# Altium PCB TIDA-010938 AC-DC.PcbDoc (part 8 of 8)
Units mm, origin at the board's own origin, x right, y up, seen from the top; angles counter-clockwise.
Board outline 280 x 180.15 mm, 4 copper layers (Top Layer, Layer 1, Layer 2, Bottom Layer), stack 1.787 mm thick; 723 components, 427 nets, 2244 pads, 2295 vias.
Unrouted connection lines stored in the file: 17.
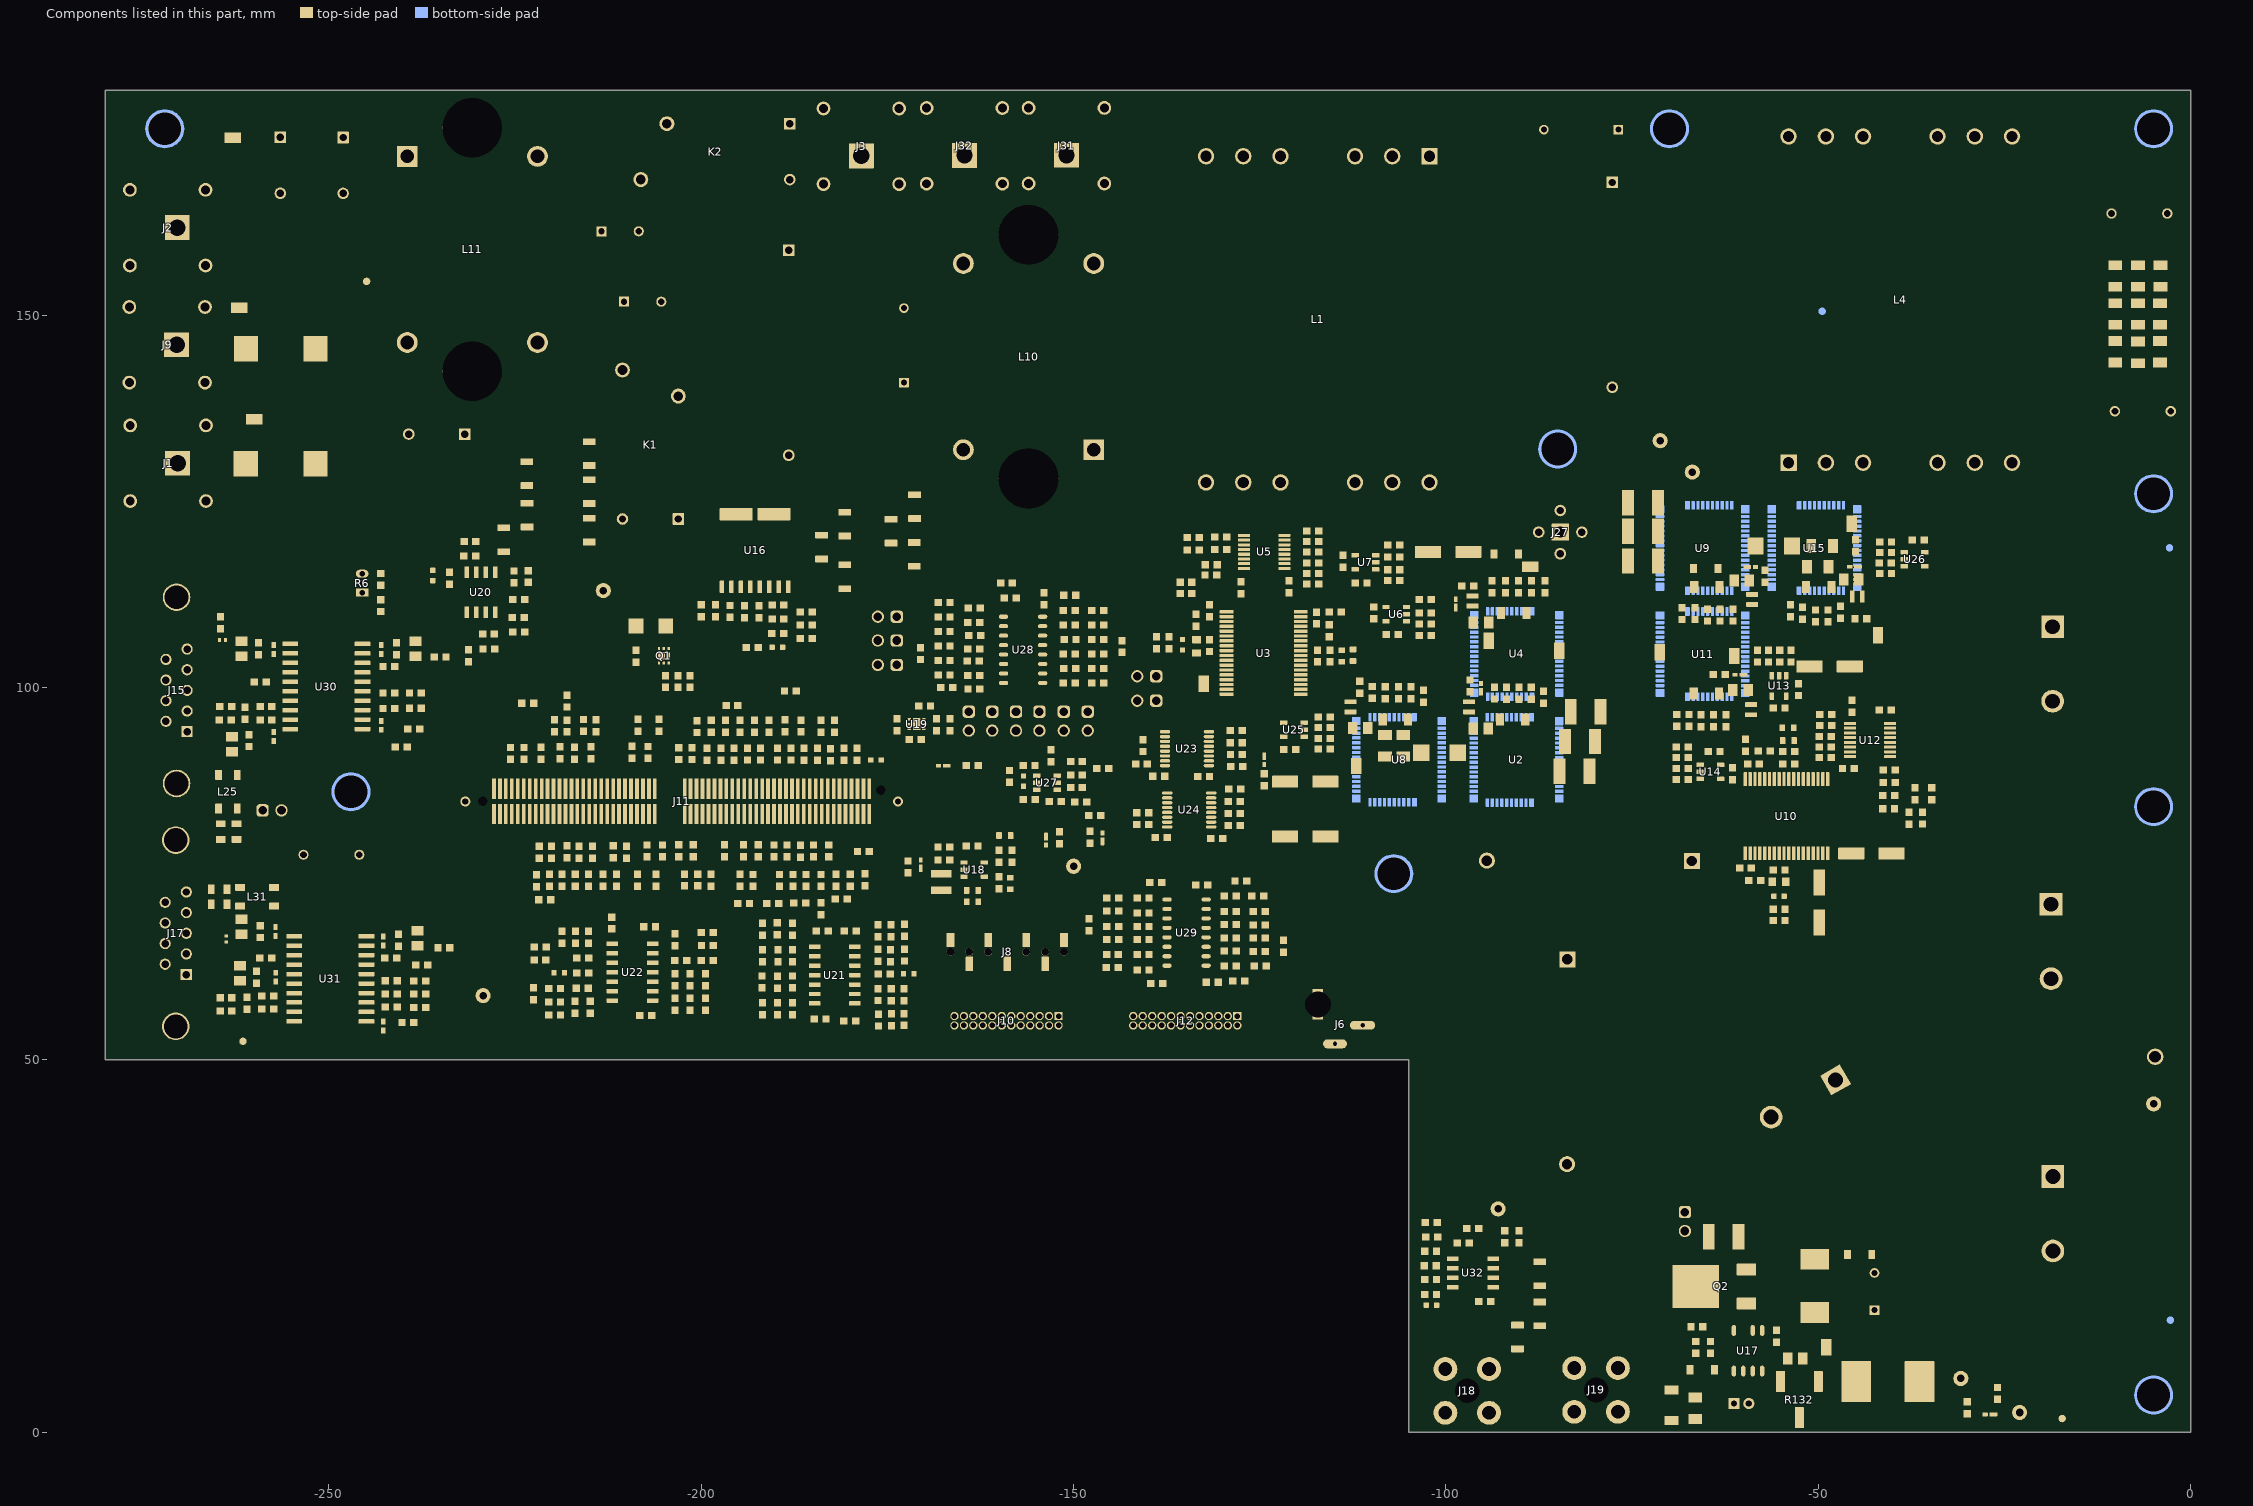
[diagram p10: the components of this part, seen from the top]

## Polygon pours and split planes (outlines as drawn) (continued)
NetR108_2 on Top Layer "TOP_LAYER_NETR108_2_P340" (solid, remove dead copper, pour order 340): -91.5,14 -91.5,15.25 -86.5,15.25 -86.5,14
SW_1 on Top Layer "TOP_LAYER_SW_1_P337" (solid, remove dead copper, pour order 337): -109,125 -109,130 -108.5,130.5 -94,130.5 -94,123 -107,123
VAC_N on Top Layer "TOP_LAYER_VAC_N_P229" (solid, pour order 229): -225.142,177.648 -225.142,162.357 -220.595,157.81 -212,157.81 -212,165.039 -215.238,168.277 -215.238,171.704 -213.815,173.126 -202.358,173.126 -200.148,175.336 -200.148,177.851 -201.571,179.273 -223.516,179.273
ACLOAD_N on Top Layer "TOP_LAYER_ACLOAD_N_P336" (solid, remove dead copper, pour order 336): -210,170 -210,163 -209,162 -209,160 -208.868,159.868 -193.868,159.868 -190,156 -186,156 -186,161 -188,163 -197,163 -204,170
ACLOAD_L on Top Layer "Top Layer-ACLOAD_L" (solid, pour order 334): 17 vertices, not listed, extent -206.625,122.504 -175,174
NetC103_1 on Top Layer "TOP_LAYER_NETC103_1_P331" (solid, remove dead copper, pour order 331): -78,169 -79,168 -80,168 -80,161 -47,161 -46,162 -46,168 -46,177 -57,177 -58,176 -58,173 -63,168 -76,168 -77,169
AC_N on Top Layer "TOP_LAYER_AC_N_P322" (solid, pour order 322): -274.367,132.537 -274.367,128.778 -271.217,125.628 -259.372,125.628 -259,126 -259,132 -258,133 -258,137.795 -260.702,137.795 -265.172,133.325 -273.554,133.325 -274.342,132.537
PE on Top Layer "TOP_LAYER_PE_P214" (solid, pour order 214): -278.294,174.516 -273.816,178.994 -249.196,178.994 -245.767,175.565 -245.767,173.025 -258.467,173.025 -265.223,166.268 -265.223,160.884 -268.347,157.759 -274.189,157.759 -278.294,161.864
NetC116_2 on Top Layer "TOP_LAYER_NETC116_2_P103" (solid, remove dead copper, pour order 103): -51.514,5.424 -48.264,5.424 -48.264,3.924 -42.926,3.924 -42.926,10.643 -50.207,17.924 -53.014,17.924 -53.514,17.424 -53.514,15.424 -52.349,14.26 -52.349,11.088 -52.756,10.682 -52.756,8.166 -51.514,6.924
12V_HVN on Top Layer "TOP_LAYER_12V_HVN_P104" (solid, remove dead copper, pour order 104): -38.354,3.988 -37.79,3.424 -29.514,3.424 -28.514,4.424 -28.514,8.924 -37.014,17.424 -44.014,17.424 -44.75,16.25 -38.354,9.764
NetC229_1 on Top Layer "TOP_LAYER_NETC229_1_P101" (solid, remove dead copper, pour order 101): -69.571,16.698 -69.571,27.448 -69.06,27.958 -63.299,27.958 -63.299,16.698
NetQ2_3 on Top Layer "TOP_LAYER_NETQ2_3_P110" (solid, remove dead copper, pour order 110): -55.268,8.938 -53.442,8.938 -53.442,12.649 -56.058,12.649 -56.311,12.396 -56.311,9.981
"DC Bus-" on Top Layer "TOP_LAYER_DC_BUS-_P089" (solid, remove dead copper, pour order 89): -55.5,78.537 -43.586,78.537 -43.586,75.914 -47.542,71.958 -53.603,71.958 -55.5,73.855
"DC Bus-" on Top Layer "TOP_LAYER_DC_BUS-_P314" (solid, pour order 314): -88.544,121.514 -85.242,124.816 -83.734,124.816 -80.85,121.931 -80.85,120.052 -83.858,117.043 -85.369,117.043 -88.519,120.193
NetR122_2 on Top Layer "TOP_LAYER_NETR122_2_P297" (solid, remove dead copper, pour order 297): -175.815,123.901 -175.815,121.818 -169.871,121.818 -169.871,123.901
NetR123_2 on Top Layer "TOP_LAYER_NETR123_2_P296" (solid, remove dead copper, pour order 296): -175.815,120.269 -175.815,118.186 -169.871,118.186 -169.871,120.269
NetR112_2 on Top Layer "TOP_LAYER_NETR112_2_P295" (solid, remove dead copper, pour order 295): -185.289,117.856 -185.289,115.773 -179.346,115.773 -179.346,117.856
NetR111_2 on Top Layer "TOP_LAYER_NETR111_2_P294" (solid, remove dead copper, pour order 294): -185.213,121.463 -185.213,119.38 -179.269,119.38 -179.269,121.463
VAC_SW+ on Top Layer "TOP_LAYER_VAC_SW+_P243" (solid, pour order 243): 18 vertices, not listed, extent -192.528,122.504 -159.076,160.884
NetR117_2 on Top Layer "TOP_LAYER_NETR117_2_P293" (solid, remove dead copper, pour order 293): -216.7,125.1 -216.7,121.768 -213.509,121.768 -213.509,125.1
NetR116_2 on Top Layer "TOP_LAYER_NETR116_2_P292" (solid, remove dead copper, pour order 292): -217.4,129.841 -217.4,127.759 -212.628,127.759 -212.628,129.841
NetR127_2 on Top Layer "TOP_LAYER_NETR127_2_P291" (solid, remove dead copper, pour order 291): -224.564,127.6 -224.564,123.774 -221.916,123.774 -221.916,127.6
NetR128_2 on Top Layer "TOP_LAYER_NETR128_2_P290" (solid, remove dead copper, pour order 290): -227.91,122.504 -227.91,120.421 -221.967,120.421 -221.967,122.504
NetC103_2 on Top Layer "TOP_LAYER_NETC103_2_P285" (solid, pour order 285): -2.409,144.526 -2.435,144.501 -2.409,144.475 -2.409,142.545 -4.34,140.614 -7.997,140.614 -8.861,139.751 -8.861,135.661 -10.817,135.661 -10.867,135.611 -11.731,136.474 -11.731,143.891 -11.172,144.45
SW_mid on Top Layer "TOP_LAYER_SW_MID_P168" (solid, remove dead copper, pour order 168): -72.5,103.012 -69.5,103.012 -69.5,105.5 -70,106 -72.5,106
12V_HVN on Top Layer "TOP_LAYER_12V_HVN_P183" (solid, remove dead copper, pour order 183): -41.689,25.269 -38.439,25.269 -38.439,28.019 -41.689,28.019
NetR77_1 on Top Layer "TOP_LAYER_NETR77_1_P272" (solid, pour order 272): -11.89,149.403 -2.696,149.403 -2.696,145.821 -11.916,145.821
NetR185_1 on Top Layer "TOP_LAYER_NETR185_1_P271" (solid, pour order 271): -11.78,154.507 -2.585,154.507 -2.585,150.925 -11.806,150.925
NetC103_1 on Top Layer "TOP_LAYER_NETC103_1_P270" (solid, pour order 270): -12.182,164.923 -9.928,164.923 -8.886,163.881 -8.886,158.775 -3.527,158.775 -2.409,157.658 -2.409,156.007 -11.604,156.007 -12.188,156.591 -12.188,164.897
"DC Bus-" on Top Layer "TOP_LAYER_DC_BUS-_P177" (solid, remove dead copper, pour order 177): -130.5,109.5 -130.5,111.5 -128,111.5 -128,109.5
"DC Bus-" on Top Layer "TOP_LAYER_DC_BUS-_P266" (solid, remove dead copper, pour order 266): -54.214,112.837 -54.214,114.837 -53.964,115.087 -49.464,115.087 -51.534,113.017 -51.534,112.837
SW_2 on Top Layer "TOP_LAYER_SW_2_P051" (solid, remove dead copper, pour order 51): -53.657,86.683 -54.157,87.183 -54.157,88.683 -53.657,88.683 -53.657,94.869 -52.843,94.869 -52.307,94.333 -52.307,91.833 -51.857,91.383 -50.11,89.637 -48.957,89.637 -47.503,88.183 -46.657,88.183 -46.657,86.683
SW_2 on Top Layer "TOP_LAYER_SW_2_P052" (solid, remove dead copper, pour order 52): -56.816,86.759 -56.816,89.059 -57.016,89.259 -57.016,90.159 -56.716,90.459 -56.016,90.459 -55.616,90.059 -55.616,88.659 -55.716,88.559 -55.716,86.759
SW_2 on Top Layer "TOP_LAYER_SW_2_P053" (solid, remove dead copper, pour order 53): -68.589,87.125 -69.789,87.125 -69.789,95.253 -65.539,95.253 -65.189,94.903 -65.189,93.853 -67.789,93.853 -68.589,93.053
"DC Bus+" on Top Layer "TOP_LAYER_DC_BUS+_P063" (solid, remove dead copper, pour order 63): -72.768,114.582 -73.25,114.1 -73.25,112.975 -72.768,112.5 -72.768,112 -70.5,112 -70,112.5 -70,115.739 -68.818,116.921 -68.818,126.318 -69.921,127.421 -72.218,127.421 -72.768,126.871
SW_2 on Top Layer "TOP_LAYER_SW_2_P074" (solid, remove dead copper, pour order 74): -64.14,100.171 -60.965,100.171 -60.965,100.662 -62.881,100.662 -63.39,101.171 -63.39,102.171 -63.64,102.421 -65.89,102.421 -68.64,99.671 -68.64,98.171 -65.983,98.171 -65.983,99.143 -65.705,99.421 -64.89,99.421
SW_2 on Top Layer "TOP_LAYER_SW_2_P199" (solid, remove dead copper, pour order 199): -47.919,104.771 -47.919,99.25 -44.125,99.25 -44.125,104.771
NetC103_2 on Top Layer "TOP_LAYER_NETC103_2_P250" (solid, pour order 250): 20 vertices, not listed, extent -150.771,133.325 -8.861,174.422
VAC_L on Top Layer "TOP_LAYER_VAC_L_P233" (solid, pour order 233): -225.026,149.24 -220.965,153.3 -209.216,153.3 -209.216,141.046 -211.553,138.709 -224.961,138.709
NetF1_1 on Top Layer "TOP_LAYER_NETF1_1_P221" (solid, pour order 221): 23 vertices, not listed, extent -259.635,130.86 -236.572,167.64
NetF2_1 on Top Layer "TOP_LAYER_NETF2_1_P222" (solid, pour order 222): -251.23,167.649 -251.221,167.64 -244.903,167.64 -244.903,167.792 -242.185,170.51 -242.185,174.625 -237.943,174.625 -233.905,170.586 -233.905,165.354 -237.68,161.578 -251.203,161.578
SN_Relays_PreCharge on Top Layer "TOP_LAYER_SN_RELAYS_PRECHARGE_P043" (solid, remove dead copper, pour order 43): -204.425,114.1 -202.402,114.102 -201.375,113.075 -201.375,108.45 -203.625,106.2 -204.5,106.2 -204.775,105.925 -204.775,102.725 -204.975,102.525 -206.025,102.525 -206.35,102.85 -206.35,112.225 -204.475,114.1
SW_1 on Top Layer "TOP_LAYER_SW_1_P056" (solid, remove dead copper, pour order 56): -117,99 -114.5,101.5 -114.5,102.5 -113.5,103.5 -112,103.5 -112,104 -120.5,104 -120.5,99
SW_1 on Top Layer "TOP_LAYER_SW_1_P200" (solid, remove dead copper, pour order 200): -103,115 -104,116 -105,117 -105,121 -101,121 -100,120 -100,115
SW_1 on Top Layer "TOP_LAYER_SW_1_P181" (solid, remove dead copper, pour order 181): -91.75,93.75 -89,93.75 -88.5,94.25 -88.5,96.5 -88.65,96.65 -89.9,96.65 -90.75,95.8 -91.75,95.8
SW_1 on Top Layer "TOP_LAYER_SW_1_P179" (solid, remove dead copper, pour order 179): -122.5,121.75 -122.5,120.295 -120.955,120.295 -120.25,121 -120.25,121.5 -120.5,121.75
"DC Bus-" on Top Layer "TOP_LAYER_DC_BUS-_P176" (solid, remove dead copper, pour order 176): -128.5,98.5 -132.5,98.5 -132.5,102.5 -131.5,103.5 -131.5,105.05 -131.05,105.05 -131.05,105.625 -128.625,105.625 -128.5,105.5
SW_1 on Top Layer "TOP_LAYER_SW_1_P174" (solid, remove dead copper, pour order 174): -90.725,114.075 -90.75,114.1 -90.75,119 -89.5,119 -86.7,116.2 -86.7,114.075
"DC Bus-" on Top Layer "TOP_LAYER_DC_BUS-_P173" (solid, remove dead copper, pour order 173): -189.25,106.25 -189.25,111.5 -186.75,111.5 -186.446,111.196 -186.446,109.377 -186.76,109.064 -186.794,109.098 -187.446,109.098 -187.446,106.354 -187.55,106.25
"DC Bus-" on Top Layer "TOP_LAYER_DC_BUS-_P172" (solid, remove dead copper, pour order 172): -122,78.75 -121.5,78.25 -119.75,78.25 -118.75,79.25 -118.75,88.75 -119.5,89.5 -120.75,89.5 -121.5,88.75 -121.5,85.75 -121.75,85.5 -123.25,85.5 -124,84.75 -124,78.75
SW_mid on Top Layer "TOP_LAYER_SW_MID_P166" (solid, remove dead copper, pour order 166): -86.25,103.25 -83.75,103.25 -83.75,106.75 -86.25,106.75
SW_1 on Top Layer "TOP_LAYER_SW_1_P076" (solid, remove dead copper, pour order 76): -95,104.953 -93.25,104.953 -93.25,107.5 -93,107.75 -89,107.75 -88.25,108.5 -88.25,110.604 -88.625,110.979 -91.75,110.979 -91.75,109.175 -91.9,109.025 -93.3,109.025 -93.5,109.225 -93.5,110 -95,110
"DC Bus-" on Layer 2 "Layer 2-DC Bus- 1" (solid, remove dead copper, pour order 196): 73 vertices, not listed, extent -246.6,0.523 -21.869,123.469
"DC Bus-" on Layer 2 "Layer 2-DC Bus-" (solid, pour order 309): 34 vertices, not listed, extent -114,62.5 -40,139
NetF2_1 on Layer 2 "LAYER_2_NETF2_1_P228" (solid, pour order 228): 25 vertices, not listed, extent -254.682,125.197 -228.952,174.625
"DC Bus-" on Layer 2 "LAYER_2_DC_BUS-_P361" (solid, remove dead copper, pour order 361): -72.5,1 -72.5,17.5 -78,17.5 -86,9.5 -86,1
NetC229_1 on Layer 2 "LAYER_2_NETC229_1_P352" (solid, remove dead copper, pour order 352): -70,16.5 -70,27.5 -63,27.5 -63,16.5
SW_1 on Layer 2 "LAYER_2_SW_1_P339" (solid, remove dead copper, pour order 339): -109,125 -109,130 -108.5,130.5 -94,130.5 -94,123 -107,123
ACLOAD_L on Layer 2 "LAYER_2_ACLOAD_L_P335" (solid, remove dead copper, pour order 335): -197,124 -193,124 -193,135 -177,151 -177,159 -175,161 -175,174 -182,174 -182,157 -197,142
NetC103_1 on Layer 2 "LAYER_2_NETC103_1_P332" (solid, remove dead copper, pour order 332): -78,169 -79,168 -80,168 -80,161 -47,161 -46,162 -46,168 -46,177 -57,177 -58,176 -58,173 -63,168 -76,168 -77,169
VAC_N on Layer 2 "LAYER_2_VAC_N_P302" (solid, pour order 302): -225.142,177.648 -225.142,162.357 -220.595,157.81 -212,157.81 -212,165.039 -215.238,168.277 -215.238,171.704 -213.815,173.126 -202.358,173.126 -200.148,175.336 -200.148,177.851 -201.571,179.273 -223.516,179.273
AC_L on Layer 2 "LAYER_2_AC_L_P325" (solid, pour order 325): -275.002,148.768 -275.002,145.009 -271.852,141.859 -259,141.859 -259,153.975 -261.388,153.975 -265.807,149.555 -274.189,149.555 -274.977,148.768
AC_N on Layer 2 "LAYER_2_AC_N_P321" (solid, pour order 321): -274.367,132.537 -274.367,128.778 -271.217,125.628 -259.372,125.628 -259,126 -259,132 -258,133 -258,137.795 -260.702,137.795 -265.172,133.325 -273.554,133.325 -274.342,132.537
NetC103_2 on Layer 2 "LAYER_2_NETC103_2_P251" (solid, pour order 251): 21 vertices, not listed, extent -150.771,133.325 -8.861,174.422
"DC Bus+" on Layer 2 "LAYER_2_DC_BUS+_P097" (solid, remove dead copper, pour order 97): -91.335,0.575 -102.688,0.575 -102.688,11.24 -102.062,11.709 -94.586,11.709 -83,23.295 -83,30 -86,33 -86,38.5 -73,38.5 -73,25.497 -91.335,7.163
"DC Bus-" on Layer 2 "LAYER_2_DC_BUS-_P119" (solid, remove dead copper, pour order 119): -24.725,112 -12.45,112 -12.45,14 -24.725,14
PE3 on Layer 2 "LAYER_2_PE3_P269" (solid, pour order 269): 17 vertices, not listed, extent -10.436,131.928 -0.631,178.714
SW_1 on Layer 2 "Layer 2-SW_1" (solid, remove dead copper, pour order 55): 27 vertices, not listed, extent -122.5,94 -86.7,122
SW_2 on Layer 2 "LAYER_2_SW_2_P050" (solid, remove dead copper, pour order 50): 30 vertices, not listed, extent -69.776,86.6 -44.776,116.2
VAC_SW+ on Layer 2 "LAYER_2_VAC_SW+_P275" (solid, pour order 275): 20 vertices, not listed, extent -192.528,122.504 -159.076,160.884
PE2 on Layer 2 "Layer 2-PE2" (solid, pour order 257): 26 vertices, not listed, extent -174,150 -65.757,178.998
PE on Layer 2 "LAYER_2_PE_P217" (solid, pour order 217): -278.294,174.516 -273.816,178.994 -249.196,178.994 -245.767,175.565 -245.767,173.025 -246.656,172.136 -259.356,172.136 -265.223,166.268 -265.223,160.884 -268.347,157.759 -274.189,157.759 -278.294,161.864
GND_ISO_COMM on Layer 2 "LAYER_2_GND_ISO_COMM_P045" (solid, remove dead copper, pour order 45): -279.7,116.5 -277.4,118.8 -258.3,118.8 -253.6,114.1 -253.6,50.7 -278.3,50.7 -279.7,52.1

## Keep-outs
Keep-Out Layer:
  text ".Layer_Name" at -281.017,-104.177 h0.5

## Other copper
Top Layer:
  pour cut-out: -114.5,74.55 ccw(c-107.2,74.55) -107.2,67.25 ccw(c-107.2,74.55) -99.9,74.55 ccw(c-107.2,74.55) -107.2,81.85 ccw(c-107.2,74.55)
  pour cut-out: -92.213,131.826 ccw(c-84.913,131.826) -84.913,124.526 ccw(c-84.913,131.826) -77.613,131.826 ccw(c-84.913,131.826) -84.913,139.126 ccw(c-84.913,131.826)
  pour cut-out: -87.75,36 ccw(c-83.75,36) -83.75,32 ccw(c-83.75,36) -79.75,36 ccw(c-83.75,36) -83.75,40 ccw(c-83.75,36)
  pour cut-out: -8.792,50.419 ccw(c-4.792,50.419) -4.792,46.419 ccw(c-4.792,50.419) -0.792,50.419 ccw(c-4.792,50.419) -4.792,54.419 ccw(c-4.792,50.419)
  pour cut-out: -12.565,5.284 ccw(c-5.265,5.284) -5.265,-2.016 ccw(c-5.265,5.284) 2.035,5.284 ccw(c-5.265,5.284) -5.265,12.584 ccw(c-5.265,5.284)
  pour cut-out: -11.994,84.199 ccw(c-4.694,84.199) -4.694,76.899 ccw(c-4.694,84.199) 2.606,84.199 ccw(c-4.694,84.199) -4.694,91.499 ccw(c-4.694,84.199)
  pour cut-out: -22.55,98.15 ccw(c-18.55,98.15) -18.55,94.15 ccw(c-18.55,98.15) -14.55,98.15 ccw(c-18.55,98.15) -18.55,102.15 ccw(c-18.55,98.15)
  pour cut-out: -22.775,60.9 ccw(c-18.775,60.9) -18.775,56.9 ccw(c-18.775,60.9) -14.775,60.9 ccw(c-18.775,60.9) -18.775,64.9 ccw(c-18.775,60.9)
  pour cut-out: -22.525,24.35 ccw(c-18.525,24.35) -18.525,20.35 ccw(c-18.525,24.35) -14.525,24.35 ccw(c-18.525,24.35) -18.525,28.35 ccw(c-18.525,24.35)
  pour cut-out: -60.344,42.311 ccw(c-56.344,42.311) -56.344,38.311 ccw(c-56.344,42.311) -52.344,42.311 ccw(c-56.344,42.311) -56.344,46.311 ccw(c-56.344,42.311)
  pour cut-out: -254.4,86.1 ccw(c-247.1,86.1) -247.1,78.8 ccw(c-247.1,86.1) -239.8,86.1 ccw(c-247.1,86.1) -247.1,93.4 ccw(c-247.1,86.1)
  pour cut-out: -254.4,86.1 ccw(c-247.1,86.1) -247.1,78.8 ccw(c-247.1,86.1) -239.8,86.1 ccw(c-247.1,86.1) -247.1,93.4 ccw(c-247.1,86.1)
  pour cut-out: -62.538,61.613 -61.038,61.613 -61.038,45.113 -62.538,45.113
  pour cut-out: -73.338,61.613 -71.838,61.613 -71.838,45.113 -73.338,45.113
  pour cut-out: -86.233,122.936 -82.956,122.936 -82.575,122.555 -82.575,119.151 -82.982,118.745 -86.385,118.745 -86.741,119.101 -86.741,122.479
  pour cut-out: -198.217,122.446 -198.217,124.605 -198.217,124.783 -198.217,124.935 -197.505,124.935 -197.505,122.446
  pour cut-out: -188.007,122.428 -188.007,124.587 -188.007,124.765 -188.007,124.917 -187.296,124.917 -187.296,122.428
  pour cut-out: -184.603,174.523 -184.476,174.65 -184.502,174.65 -184.527,174.676
  pour cut-out: -84.75,61.5 -83.25,61.5 -83.25,45 -84.75,45
  text ".Layer_Name" at -281.017,-104.177 h0.5
Layer 1:
  pour cut-out: -8.994,44.094 ccw(c-4.994,44.094) -4.994,40.094 ccw(c-4.994,44.094) -0.994,44.094 ccw(c-4.994,44.094) -4.994,48.094 ccw(c-4.994,44.094)
  pour cut-out: -22.55,108.15 ccw(c-18.55,108.15) -18.55,104.15 ccw(c-18.55,108.15) -14.55,108.15 ccw(c-18.55,108.15) -18.55,112.15 ccw(c-18.55,108.15)
  pour cut-out: -22.775,70.9 ccw(c-18.775,70.9) -18.775,66.9 ccw(c-18.775,70.9) -14.775,70.9 ccw(c-18.775,70.9) -18.775,74.9 ccw(c-18.775,70.9)
  pour cut-out: -22.525,34.35 ccw(c-18.525,34.35) -18.525,30.35 ccw(c-18.525,34.35) -14.525,34.35 ccw(c-18.525,34.35) -18.525,38.35 ccw(c-18.525,34.35)
  pour cut-out: -51.684,47.311 ccw(c-47.684,47.311) -47.684,43.311 ccw(c-47.684,47.311) -43.684,47.311 ccw(c-47.684,47.311) -47.684,51.311 ccw(c-47.684,47.311)
  pour cut-out: -87.7,63.5 ccw(c-83.7,63.5) -83.7,59.5 ccw(c-83.7,63.5) -79.7,63.5 ccw(c-83.7,63.5) -83.7,67.5 ccw(c-83.7,63.5)
  pour cut-out: -254.4,86.1 ccw(c-247.1,86.1) -247.1,78.8 ccw(c-247.1,86.1) -239.8,86.1 ccw(c-247.1,86.1) -247.1,93.4 ccw(c-247.1,86.1)
  pour cut-out: -63.05,62.1 -60.55,62.1 -60.55,44.737 -63.05,44.737
  pour cut-out: -73.85,62.2 -71.35,62.2 -71.35,44.737 -73.85,44.737
  pour cut-out: -85.25,61.5 -82.75,61.5 -82.75,44.737 -85.25,44.737
Layer 2:
  pour cut-out: -92.213,131.826 ccw(c-84.913,131.826) -84.913,124.526 ccw(c-84.913,131.826) -77.613,131.826 ccw(c-84.913,131.826) -84.913,139.126 ccw(c-84.913,131.826)
  pour cut-out: -22.55,98.15 ccw(c-18.55,98.15) -18.55,94.15 ccw(c-18.55,98.15) -14.55,98.15 ccw(c-18.55,98.15) -18.55,102.15 ccw(c-18.55,98.15)
  pour cut-out: -22.775,60.9 ccw(c-18.775,60.9) -18.775,56.9 ccw(c-18.775,60.9) -14.775,60.9 ccw(c-18.775,60.9) -18.775,64.9 ccw(c-18.775,60.9)
  pour cut-out: -22.525,24.35 ccw(c-18.525,24.35) -18.525,20.35 ccw(c-18.525,24.35) -14.525,24.35 ccw(c-18.525,24.35) -18.525,28.35 ccw(c-18.525,24.35)
  pour cut-out: -98.5,76.75 ccw(c-94.5,76.75) -94.5,72.75 ccw(c-94.5,76.75) -90.5,76.75 ccw(c-94.5,76.75) -94.5,80.75 ccw(c-94.5,76.75)
  pour cut-out: -254.4,86.1 ccw(c-247.1,86.1) -247.1,78.8 ccw(c-247.1,86.1) -239.8,86.1 ccw(c-247.1,86.1) -247.1,93.4 ccw(c-247.1,86.1)
  pour cut-out: -57.069,127.27 -57.069,133.27 -45.8,133.27 -45.8,127.27
  pour cut-out: -69.05,127 -69.05,131.183 -64.6,131.183 -64.6,127
  pour cut-out: -188.001,122.439 -188.001,124.598 -188.001,124.776 -188.001,124.928 -187.29,124.928 -187.29,122.439
  pour cut-out: -58,45 -54,45 -49,50 -44.5,50 -44.5,47 -52,39.5 -58,39.5 -59.5,41 -59.5,43.5
Bottom Layer:
  pour cut-out: -57.504,101.454 ccw(c-57.004,101.454) -57.004,100.954 ccw(c-57.004,101.454) -56.504,101.454 ccw(c-57.004,101.454) -57.004,101.954 ccw(c-57.004,101.454)
  pour cut-out: -102.454,105.804 ccw(c-101.954,105.804) -101.954,105.304 ccw(c-101.954,105.804) -101.454,105.804 ccw(c-101.954,105.804) -101.954,106.304 ccw(c-101.954,105.804)
  pour cut-out: -104.504,116.954 ccw(c-104.004,116.954) -104.004,116.454 ccw(c-104.004,116.954) -103.504,116.954 ccw(c-104.004,116.954) -104.004,117.454 ccw(c-104.004,116.954)
  pour cut-out: -103.504,116.954 ccw(c-103.004,116.954) -103.004,116.454 ccw(c-103.004,116.954) -102.504,116.954 ccw(c-103.004,116.954) -103.004,117.454 ccw(c-103.004,116.954)
  pour cut-out: -103.504,115.954 ccw(c-103.004,115.954) -103.004,115.454 ccw(c-103.004,115.954) -102.504,115.954 ccw(c-103.004,115.954) -103.004,116.454 ccw(c-103.004,115.954)
  pour cut-out: -102.504,115.954 ccw(c-102.004,115.954) -102.004,115.454 ccw(c-102.004,115.954) -101.504,115.954 ccw(c-102.004,115.954) -102.004,116.454 ccw(c-102.004,115.954)
  pour cut-out: -102.496,117.046 ccw(c-101.996,117.046) -101.996,116.546 ccw(c-101.996,117.046) -101.496,117.046 ccw(c-101.996,117.046) -101.996,117.546 ccw(c-101.996,117.046)
  pour cut-out: -102.524,119.528 ccw(c-102.024,119.528) -102.024,119.028 ccw(c-102.024,119.528) -101.524,119.528 ccw(c-102.024,119.528) -102.024,120.028 ccw(c-102.024,119.528)
  pour cut-out: -22.525,34.35 ccw(c-18.525,34.35) -18.525,30.35 ccw(c-18.525,34.35) -14.525,34.35 ccw(c-18.525,34.35) -18.525,38.35 ccw(c-18.525,34.35)
  pour cut-out: -92.213,131.826 ccw(c-84.913,131.826) -84.913,124.526 ccw(c-84.913,131.826) -77.613,131.826 ccw(c-84.913,131.826) -84.913,139.126 ccw(c-84.913,131.826)
  pour cut-out: -114.724,74.66 ccw(c-107.424,74.66) -107.424,67.36 ccw(c-107.424,74.66) -100.124,74.66 ccw(c-107.424,74.66) -107.424,81.96 ccw(c-107.424,74.66)
  pour cut-out: -12.444,84.149 ccw(c-5.144,84.149) -5.144,76.849 ccw(c-5.144,84.149) 2.156,84.149 ccw(c-5.144,84.149) -5.144,91.449 ccw(c-5.144,84.149)
  pour cut-out: -22.55,108.15 ccw(c-18.55,108.15) -18.55,104.15 ccw(c-18.55,108.15) -14.55,108.15 ccw(c-18.55,108.15) -18.55,112.15 ccw(c-18.55,108.15)
  pour cut-out: -22.775,70.9 ccw(c-18.775,70.9) -18.775,66.9 ccw(c-18.775,70.9) -14.775,70.9 ccw(c-18.775,70.9) -18.775,74.9 ccw(c-18.775,70.9)
  pour cut-out: -57.794,112.174 ccw(c-57.294,112.174) -57.294,111.674 ccw(c-57.294,112.174) -56.794,112.174 ccw(c-57.294,112.174) -57.294,112.674 ccw(c-57.294,112.174)
  pour cut-out: -63.054,114.954 ccw(c-62.554,114.954) -62.554,114.454 ccw(c-62.554,114.954) -62.054,114.954 ccw(c-62.554,114.954) -62.554,115.454 ccw(c-62.554,114.954)
  pour cut-out: -61.994,108.124 ccw(c-61.494,108.124) -61.494,107.624 ccw(c-61.494,108.124) -60.994,108.124 ccw(c-61.494,108.124) -61.494,108.624 ccw(c-61.494,108.124)
  pour cut-out: -65.386,108.124 ccw(c-64.886,108.124) -64.886,107.624 ccw(c-64.886,108.124) -64.386,108.124 ccw(c-64.886,108.124) -64.886,108.624 ccw(c-64.886,108.124)
  pour cut-out: -96.304,98.054 ccw(c-95.804,98.054) -95.804,97.554 ccw(c-95.804,98.054) -95.304,98.054 ccw(c-95.804,98.054) -95.804,98.554 ccw(c-95.804,98.054)
  pour cut-out: -101.466,111.566 ccw(c-100.966,111.566) -100.966,111.066 ccw(c-100.966,111.566) -100.466,111.566 ccw(c-100.966,111.566) -100.966,112.066 ccw(c-100.966,111.566)
  pour cut-out: -101.5,119.5 ccw(c-101,119.5) -101,119 ccw(c-101,119.5) -100.5,119.5 ccw(c-101,119.5) -101,120 ccw(c-101,119.5)
  pour cut-out: -101.504,115.954 ccw(c-101.004,115.954) -101.004,115.454 ccw(c-101.004,115.954) -100.504,115.954 ccw(c-101.004,115.954) -101.004,116.454 ccw(c-101.004,115.954)
  pour cut-out: -96.971,114.58 ccw(c-96.471,114.58) -96.471,114.08 ccw(c-96.471,114.58) -95.971,114.58 ccw(c-96.471,114.58) -96.471,115.08 ccw(c-96.471,114.58)
  pour cut-out: -89.55,117.005 ccw(c-89.05,117.005) -89.05,116.505 ccw(c-89.05,117.005) -88.55,117.005 ccw(c-89.05,117.005) -89.05,117.505 ccw(c-89.05,117.005)
  pour cut-out: -88.55,117.005 ccw(c-88.05,117.005) -88.05,116.505 ccw(c-88.05,117.005) -87.55,117.005 ccw(c-88.05,117.005) -88.05,117.505 ccw(c-88.05,117.005)
  pour cut-out: -88.55,116.005 ccw(c-88.05,116.005) -88.05,115.505 ccw(c-88.05,116.005) -87.55,116.005 ccw(c-88.05,116.005) -88.05,116.505 ccw(c-88.05,116.005)
  pour cut-out: -89.054,115.604 ccw(c-88.554,115.604) -88.554,115.104 ccw(c-88.554,115.604) -88.054,115.604 ccw(c-88.554,115.604) -88.554,116.104 ccw(c-88.554,115.604)
  pour cut-out: -89.55,116.005 ccw(c-89.05,116.005) -89.05,115.505 ccw(c-89.05,116.005) -88.55,116.005 ccw(c-89.05,116.005) -89.05,116.505 ccw(c-89.05,116.005)
  pour cut-out: -93.471,101.333 ccw(c-92.971,101.333) -92.971,100.833 ccw(c-92.971,101.333) -92.471,101.333 ccw(c-92.971,101.333) -92.971,101.833 ccw(c-92.971,101.333)
  pour cut-out: -90.704,101.354 ccw(c-90.204,101.354) -90.204,100.854 ccw(c-90.204,101.354) -89.704,101.354 ccw(c-90.204,101.354) -90.204,101.854 ccw(c-90.204,101.354)
  pour cut-out: -254.5,86.55 ccw(c-247.2,86.55) -247.2,79.25 ccw(c-247.2,86.55) -239.9,86.55 ccw(c-247.2,86.55) -247.2,93.85 ccw(c-247.2,86.55)
  pour cut-out: -87,115 -90,115 -90,126.5 -87,126.5
  pour cut-out: -198.217,122.446 -198.217,124.605 -198.217,124.783 -198.217,124.935 -197.505,124.935 -197.505,122.446
  pour cut-out: -86.534,100.69 -86.534,98.552 -85.366,98.552 -85.34,98.577 -85.69,98.927 -85.69,100 -85.844,100
  pour cut-out: -48.5,50 -43.949,50 -43.949,43.303 -49.355,37.897 -58.283,37.897 -60.449,40.063 -60.449,44.803 -59.449,45.803 -52.697,45.803
  text ".Layer_Name" at -281.017,-104.177 h0.5

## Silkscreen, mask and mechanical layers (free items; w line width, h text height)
Top Overlay:
  drawing of 188 lines, arcs and shapes, not listed
  text "PE" at -143,176.1 h2
  text "PE" at -270,170 h2
  text "L1" at -184.4,163.6 h2
  text "N" at -170.5,161.8 h2.1
  text "L1" at -263.6,153 h2
  text "N" at -263.3,135.5 h2.1
  text "DC Bus-" at -69.592,134.163 h1.52
  text "SW2" at -71.98,128.6 h1.52
  text "SW1" at -91.665,124.409 h1.52
  text "S5" at -140.848,120.152 h0.89
  text "S1" at -140.848,117.652 h0.89
  text "DC Bus-" at -80.819,106.35 h1.52
  text "S6" at -45.848,85.652 h0.89
  text "S3" at -44.348,82.152 h0.89
  text ".PRJ_Number" at -216.728,50.824 h3.05
  text "VER: .PCB_Rev" at -189.652,50.789 h3.05
  text "DC Bus+" at -1.647,48.743 h1.52 r90
  text "DC Bus-" at -2.003,40.767 h1.52 r90
  text "12V" at -32.41,11.024 h1.52
  text "DC-" at -74.397,7.618 h2.1
  text "DC+" at -91.335,7.186 h2.1
  text ".Layer_Name" at -281.017,-104.177 h0.5
Bottom Overlay:
  text ".Layer_Name" at -281.017,-104.177 h0.5
Top Paste:
  text ".Layer_Name" at -281.017,-104.177 h0.5
Bottom Paste:
  text ".Layer_Name" at -281.017,-104.177 h0.5
Top Solder:
  region: -8.531,174.977 ccw(c-5.031,174.977) -5.031,171.477 ccw(c-5.031,174.977) -1.531,174.977 ccw(c-5.031,174.977) -5.031,178.477 ccw(c-5.031,174.977)
  region: -73.531,174.977 ccw(c-70.031,174.977) -70.031,171.477 ccw(c-70.031,174.977) -66.531,174.977 ccw(c-70.031,174.977) -70.031,178.477 ccw(c-70.031,174.977)
  region: -275.531,174.977 ccw(c-272.031,174.977) -272.031,171.477 ccw(c-272.031,174.977) -268.531,174.977 ccw(c-272.031,174.977) -272.031,178.477 ccw(c-272.031,174.977)
  text ".Layer_Name" at -281.017,-104.177 h0.5
  text ".Layer_Name" at -281.017,-104.177 h0.5
Bottom Solder:
  text ".Layer_Name" at -281.017,-104.177 h0.5
Drill Guide:
  text ".Layer_Name" at -281.017,-104.177 h0.5
M1 Board Outline:
  lines w0.5: -279.8,50 -279.8,180.2 ; -279.8,50 -104.7,50 ; -279.8,50 -279.8,180.2 ; -279.8,50 -104.7,50 ; -279.8,180.2 0,180.2 ; -279.8,180.2 0,180.2 ; -104.7,0 0,0 ; -104.7,0 -104.7,50 ; -104.7,0 0,0 ; -104.7,0 -104.7,50 ; -104.7,0 -104.7,50 ; -104.7,0 0,0 ; -104.7,50 -279.8,50 -279.8,180.2 0,180.2 ; 0,0 0,180.2 ; 0,0 0,180.2 ; 0,0 0,180.2 ; -260,107.75 -260,120.75 -247.5,120.75 -247.5,107.75 -260,107.75
M2 Board Dimensions:
  rectangle: -295.673,-89.356 -292.498,-86.181
  rectangle: -292.498,-92.531 -282.973,-89.356
  lines w0.178: -295.673,-89.356 -270.273,-89.356 ; -292.498,-92.531 -292.498,-86.181 ; -289.323,-92.531 -289.323,-86.181 ; -282.973,-92.531 -282.973,-86.181 ; -276.623,-92.531 -276.623,-86.181 ; -295.673,-92.531 -295.673,-86.181 -270.273,-86.181 -270.273,-92.531 -295.673,-92.531
  text ".Layer_Name" at -281.017,-104.177 h0.5
M3 3D STEP Top:
  text ".Layer_Name" at -281.017,-104.177 h0.5
M4 3D STEP Bottom:
  text ".Layer_Name" at -281.017,-104.177 h0.5
M5 Assembly Top:
  lines w0.254: -302.3,-106.01 -135.45,-105.997 ; -302.3,-100.832 -135.399,-100.832 ; -263.059,-111.162 -302.3,-111.162 ; -240.479,-111.162 -240.479,-95.668 ; -208.297,-100.832 -208.297,-95.668 ; -186.961,-100.832 -186.961,-95.668 ; -171.162,-111.327 -171.162,-106.175 ; -302.3,-111.162 -302.3,-95.668 ; -302.3,-111.162 -302.3,-95.668 ; -302.3,-111.162 -201.363,-111.162 -135.399,-111.162 -135.399,-95.668 -302.3,-95.668
  text "COMPONENTS MARKED 'DNP' SHOULD NOT BE POPULATED." at -266.374,-90.461 h0.5
  text "ASSEMBLY VARIANT:" at -266.387,-93.394 h0.5
  text ".VariantName" at -240.072,-93.394 h0.5
  text "PCB VIEWED FROM TOP SIDE" at -301.477,-99.025 h0.5
  text "BOARD #:" at -238.574,-99.025 h0.5
  text ".PRJ_Number" at -224.718,-99.025 h0.5
  text "REV:" at -203.268,-99.025 h0.5
  text ".PCB_Rev" at -195.864,-99.025 h0.5
  text "SVN REV:" at -181.983,-99.025 h0.5
  text ".VersionControl_RevNumber" at -169.13,-99.025 h0.5
  text "TID #:" at -238.574,-104.189 h0.5
  text ".TID" at -224.718,-104.189 h0.5
  text "PLOT NAME =" at -301.477,-109.405 h0.5
  text ".plot_File_Name" at -281.017,-109.405 h0.5
  text "GENERATED    :" at -238.523,-109.405 h0.5
  text ".Print_Date" at -216.438,-109.405 h0.5
  text ".Print_Time" at -197.921,-109.405 h0.5
  text "TEXAS INSTRUMENTS" at -165.803,-109.405 h0.5
M6 Assembly Bottom:
  lines w0.254: -302.3,-106.01 -135.412,-106.01 ; -302.3,-100.845 -135.412,-100.845 ; -267.339,-111.34 -267.339,-106.188 ; -251.54,-100.845 -251.54,-95.68 ; -230.204,-100.845 -230.204,-95.68 ; -198.023,-111.174 -198.023,-95.68 ; -175.442,-111.174 -135.424,-111.174 -135.424,-95.68 -302.3,-95.68 -302.3,-111.174 -237.139,-111.174 -135.412,-111.174 -135.412,-95.68
  text "COMPONENTS MARKED 'DNP' SHOULD NOT BE POPULATED." at -140.682,-90.448 h0.5
  text ".VariantName" at -167.2,-93.394 h0.5
  text "ASSEMBLY VARIANT:" at -140.809,-93.394 h0.5
  text ".VersionControl_RevNumber" at -269.371,-99.038 h0.5
  text "SVN REV:" at -256.519,-99.038 h0.5
  text ".PCB_Rev" at -242.638,-99.038 h0.5
  text "REV:" at -235.234,-99.038 h0.5
  text ".PRJ_Number" at -213.783,-99.038 h0.5
  text "BOARD #:" at -199.928,-99.038 h0.5
  text "PCB VIEWED FROM BOTTOM SIDE" at -137.025,-99.038 h0.5
  text ".TID" at -213.783,-104.202 h0.5
  text "TID #:" at -199.928,-104.202 h0.5
  text "TEXAS INSTRUMENTS" at -272.699,-109.418 h0.5
  text ".Print_Time" at -240.58,-109.418 h0.5
  text ".Print_Date" at -222.064,-109.418 h0.5
  text "GENERATED    :" at -199.978,-109.418 h0.5
  text ".plot_File_Name" at -157.484,-109.418 h0.5
  text "PLOT NAME =" at -137.025,-109.418 h0.5
M9 Title Sheet:
  drawing of 56 lines, arcs and shapes, not listed
  text "1" at -268.118,235.735 h1.78
  text "2" at -183.646,235.735 h1.78
  text "3" at -99.064,235.735 h1.78
  text "4" at -14.355,235.735 h1.78
  text "5" at 70.1,235.735 h1.78
  text "6" at 154.809,235.735 h1.78
  text "A" at -306.76,190.574 h1.78
  text "A" at 193.62,190.574 h1.78
  text "B" at -306.76,95.324 h1.78
  text "B" at 193.62,95.324 h1.78
  text "C" at -306.76,0.074 h1.78
  text "C" at 193.62,0.074 h1.78
  text "D" at -306.76,-95.176 h1.78
  text "D" at 193.62,-95.176 h1.78
  text "PROJECT TITLE:" at 115.032,-97.335 h1.14
  text ".PRJ_Title" at 116.302,-100.721 h1.78
  text "DESIGNED FOR:" at 115.032,-104.98 h1.14
  text ".PRJ_Customer" at 116.302,-108.536 h1.78
  text "FILE NAME:" at 115.032,-112.6 h1.14
  text ".PCB_File_Name_No_Path" at 116.302,-115.648 h1.78
  text "Texas Instruments (TI) and/or its licensors do not warrant the accuracy or completeness of this specification" at -11.193,-119.759 h1.14
  text "ENGINEER:" at 115.032,-119.966 h1.14
  text "LAYOUT BY:" at 153.259,-119.966 h1.14
  text "or any information contained therein. TI and/or its licensors do not warrant that this design will meet" at -12.336,-122.621 h1.14
  text ".PRJ_Engineer" at 116.302,-123.903 h1.78
  text ".PCB_Layout" at 154.542,-123.903 h1.78
  text "the specifications, will be suitable for your application or fit for any particular purpose, or will operate in" at -12.336,-125.482 h1.14
  text ".Layer_Name" at -280.344,-125.958 h1.52
  text "ALTIUM DESIGNER VERSION:" at 153.259,-127.84 h1.14
  text "an implementation. TI and/or its licensors do not warrant that the design is production worthy. You should" at -12.336,-128.344 h1.14
  text "completely validate and test your design implementation to confirm the system functionality for your application." at -11.193,-131.206 h1.14
  text ".print_Scale" at 116.302,-131.227 h1.78
  text ".Application_BuildNumber" at 154.542,-131.227 h1.78
  text "1" at -268.118,-137.645 h1.78
  text "2" at -183.646,-137.645 h1.78
  text "3" at -99.064,-137.645 h1.78
  text "4" at -14.355,-137.645 h1.78
  text "5" at 70.1,-137.645 h1.78
  text "6" at 154.809,-137.645 h1.78
M10 Fab Notes:
  text ".Layer_Name" at -281.017,-104.177 h0.5
M11 Gerber Information:
  lines w0.254: -302.3,-105.997 -135.45,-105.997 ; -302.3,-100.832 -135.299,-100.832 ; -263.059,-111.162 -302.3,-111.162 ; -240.479,-111.162 -240.479,-95.668 ; -208.297,-100.832 -208.297,-95.668 ; -186.961,-100.832 -186.961,-95.668 ; -171.162,-111.327 -171.162,-106.175 ; -302.3,-111.162 -302.3,-106.511 -302.3,-100.318 -302.3,-95.668 ; -302.3,-111.162 -302.3,-95.668 ; -302.3,-111.162 -201.363,-111.162 -135.399,-111.162 -135.399,-95.668 -302.3,-95.668
  text "ALL ARTWORK VIEWED FROM TOP SIDE" at -301.477,-99.025 h0.5
  text "BOARD #:" at -238.574,-99.025 h0.5
  text ".PRJ_Number" at -224.718,-99.025 h0.5
  text "REV:" at -203.268,-99.025 h0.5
  text ".PCB_Rev" at -195.864,-99.025 h0.5
  text "SVN REV:" at -181.983,-99.025 h0.5
  text ".VersionControl_RevNumber" at -169.13,-99.025 h0.5
  text "LAYER NAME =" at -301.477,-104.177 h0.5
  text "TID #:" at -238.574,-104.189 h0.5
  text ".TID" at -224.718,-104.189 h0.5
  text "PLOT NAME =" at -301.477,-109.405 h0.5
  text ".plot_File_Name" at -281.017,-109.405 h0.5
  text "GENERATED    :" at -238.523,-109.405 h0.5
  text ".Print_Date" at -216.438,-109.405 h0.5
  text ".Print_Time" at -197.921,-109.405 h0.5
  text "TEXAS INSTRUMENTS" at -165.803,-109.405 h0.5
M12 Stackup:
  text ".Layer_Name" at -281.017,-104.177 h0.5
M13 Component Bodies Top:
  text ".Layer_Name" at -281.017,-104.177 h0.5
M14 Component Bodies Bottom:
  text ".Layer_Name" at -281.017,-104.177 h0.5
M15 Courtyards Top:
  text ".Layer_Name" at -281.017,-104.177 h0.5
M16 Courtyards Bottom:
  text ".Layer_Name" at -281.017,-104.177 h0.5
Drill Drawing:
  text ".Layer_Name" at -281.017,-104.177 h0.5
M17 Embedded Cavity:
  text ".Layer_Name" at -281.017,-104.177 h0.5
M18 Embedded Assembly:
  text ".Layer_Name" at -281.017,-104.177 h0.5
M19 Embedded Keepout:
  text ".Layer_Name" at -281.017,-104.177 h0.5
Mech Layer Outline:
  lines w0.001: -280,50 -105,50 -105,0 0,0 0,180.15 -280,180.15 -280,50 ; -260,107.75 -260,120.75 -247.5,120.75 -247.5,107.75 -260,107.75

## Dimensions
-104.7,0 to -279.75,180 on M2 Board Dimensions
-279.8,180.2 to 0,0 on M2 Board Dimensions
-295.673,-92.531 to -270.273,-92.531 on M2 Board Dimensions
